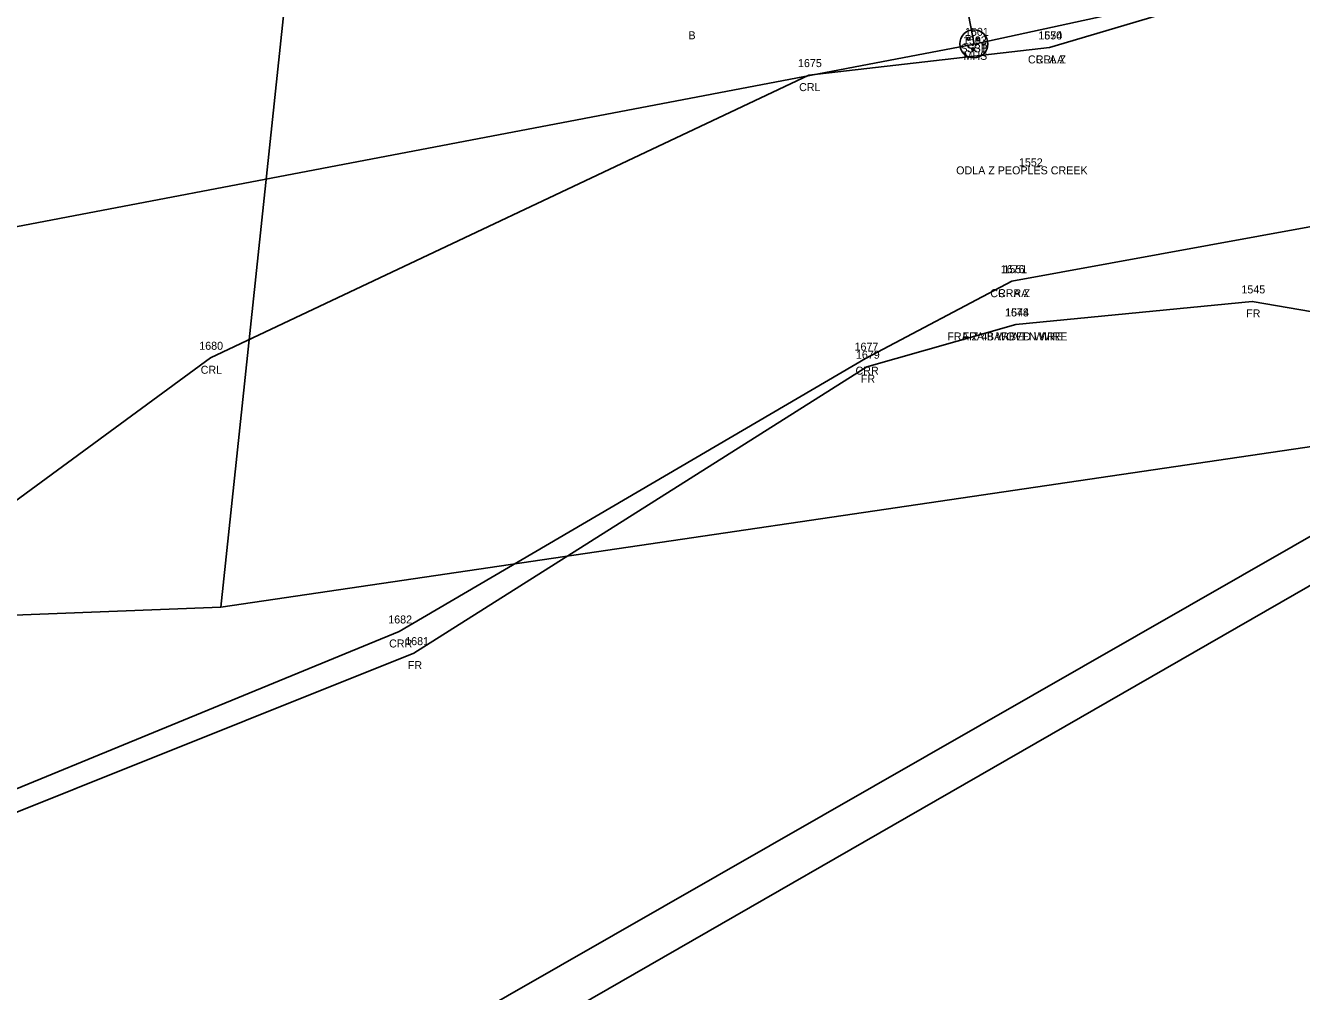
# Model space of a CAD drawing. Extents: x 1812113 to 1819860, y 1177290 to 1181185.
# Drawn here: x 1813371.7 to 1813531.1, y 1178588.3 to 1178709.1 of the extents above; entities that cross this region are included whole.
import ezdxf

# ---------------------------------------------------------------- set-up
doc = ezdxf.new("R2010")
doc.units = 0
for name, color, linetype in [('RD_EX_Bldg_txCode', 7, 'Continuous'), ('RD_EX_DR_Inlet', 7, 'Continuous'), ('RD_EX_DV_Prop', 7, 'Continuous'), ('RD_EX_Fence_Other', 7, 'Continuous'), ('RD_EX_Fence_Other_txCode', 7, 'Continuous'), ('RD_EX_H2O', 7, 'Continuous'), ('RD_EX_H2O_txCode', 7, 'Continuous'), ('RD_EX_Misc', 7, 'Continuous'), ('RD_EX_UT', 7, 'Continuous'), ('RD_EX_UT_txCode', 7, 'Continuous'), ('RD_SMD_Locator', 7, 'Continuous')]:
    doc.layers.add(name, color=color, linetype=linetype)

msp = doc.modelspace()

# ---------------------------------------------------------------- linework, layer by layer
at = {"layer": 'RD_EX_DR_Inlet'}
for centre, radius in [((1813490.17, 1178706.82), 1.75), ((1813489.51, 1178707.45), 0.175), ((1813490.09, 1178706.16), 0.175), ((1813490.73, 1178707.38), 0.175)]:
    msp.add_circle(centre, radius, dxfattribs=at)
at = {"layer": 'RD_EX_DV_Prop'}
for p, q in [((1813409.98, 1178767.65), (1813396.08, 1178636.38)), ((1813396.08, 1178636.38), (1813534.09, 1178656.72)), ((1813247.98, 1178630.56), (1813396.08, 1178636.38))]:
    msp.add_line(p, q, dxfattribs=at)
at = {"layer": 'RD_EX_Fence_Other'}
for points in [[(1813495.44, 1178671.73), (1813524.97, 1178674.61), (1813567.3, 1178667.34), (1813625.77, 1178659.53), (1813676.75, 1178657.94), (1813689.16, 1178653.47)], [(1813495.44, 1178671.73), (1813476.81, 1178666.44), (1813420.19, 1178630.62), (1813335.47, 1178596.68), (1813279.97, 1178607.5)]]:
    msp.add_lwpolyline(points, dxfattribs=at)
at = {"layer": 'RD_EX_H2O'}
for points in [[(1813499.62, 1178706.37), (1813533.11, 1178716.31), (1813566.87, 1178706.45), (1813581.02, 1178703.79), (1813602.73, 1178697.66), (1813630.18, 1178688.94), (1813658.74, 1178690.22), (1813683.52, 1178690.56), (1813733.77, 1178695.63), (1813767.86, 1178725.16), (1813778.94, 1178729.95)], [(1813499.62, 1178706.37), (1813469.57, 1178702.91), (1813394.78, 1178667.56), (1813339.87, 1178627.25), (1813279.53, 1178636.34)], [(1813494.93, 1178677.14), (1813538.08, 1178685.02), (1813548.67, 1178684.4), (1813554.06, 1178674.83), (1813572.78, 1178667.8), (1813599.8, 1178663.18), (1813623.26, 1178662.12), (1813655.35, 1178662.6), (1813687.65, 1178668.53), (1813720.68, 1178667.78), (1813740.16, 1178669.89), (1813749.02, 1178672.08), (1813765.42, 1178660.89)], [(1813494.93, 1178677.14), (1813476.64, 1178667.45), (1813418.36, 1178633.33), (1813336.03, 1178599.49), (1813281.53, 1178610.55)]]:
    msp.add_lwpolyline(points, dxfattribs=at)
at = {"layer": 'RD_EX_Misc'}
for points in [[(1813405.71, 1178572.74), (1813779.17, 1178786.7), (1813799.35, 1179222.21)], [(1813408.47, 1178567.92), (1813786.33, 1178785.29), (1813804.76, 1179221.83)]]:
    msp.add_lwpolyline(points, dxfattribs=at)
at = {"layer": 'RD_EX_UT'}
for points in [[(1812996.89, 1178919.95), (1813204.49, 1178832.44), (1813481.3, 1178753.03), (1813490.2, 1178706.76)], [(1813817.45, 1178777.9), (1813490.2, 1178706.76), (1813294.33, 1178669.42)]]:
    msp.add_lwpolyline(points, dxfattribs=at)
at = {"layer": 'RD_SMD_Locator'}
for centre in [(1813490.2, 1178706.76), (1813490.2, 1178706.76), (1813499.62, 1178706.37), (1813499.62, 1178706.37), (1813469.57, 1178702.91), (1813497.15, 1178691.5), (1813494.93, 1178677.14), (1813494.93, 1178677.14), (1813524.97, 1178674.61), (1813495.44, 1178671.73), (1813495.44, 1178671.73), (1813394.78, 1178667.56), (1813476.64, 1178667.45), (1813476.81, 1178666.44), (1813418.36, 1178633.33), (1813420.19, 1178630.62)]:
    msp.add_circle(centre, 0.001, dxfattribs=at)

# ---------------------------------------------------------------- texts
at = {"layer": 'RD_EX_Bldg_txCode'}
msp.add_text('B', height=1, dxfattribs=at).set_placement((1813454.51, 1178707.39))
at = {"layer": 'RD_EX_Fence_Other_txCode'}
for s, p in [('1545', (1813523.62, 1178675.61)), ('1678', (1813494.07, 1178672.73)), ('1544', (1813494.1, 1178672.73)), ('FR', (1813524.21, 1178672.61)), ('FRA Z 48 WOVEN WIRE', (1813486.87, 1178669.73)), ('FRA BARBED WIRE', (1813488.77, 1178669.73)), ('1679', (1813475.44, 1178667.44)), ('FR', (1813476.05, 1178664.44)), ('1681', (1813419.11, 1178631.62)), ('FR', (1813419.44, 1178628.62))]:
    msp.add_text(s, height=1, dxfattribs=at).set_placement(p)
at = {"layer": 'RD_EX_H2O_txCode'}
for s, p in [('1550', (1813498.23, 1178707.37)), ('1674', (1813498.25, 1178707.37)), ('1675', (1813468.2, 1178703.91)), ('CRLA Z', (1813496.94, 1178704.37)), ('CRLA', (1813497.9, 1178704.37)), ('CRL', (1813468.34, 1178700.91)), ('1552', (1813495.81, 1178691.5)), ('ODLA Z PEOPLES CREEK', (1813487.97, 1178690.5)), ('1676', (1813493.54, 1178678.14)), ('1551', (1813493.87, 1178678.14)), ('CRRA Z', (1813492.23, 1178675.14)), ('CRRA', (1813493.19, 1178675.14)), ('1680', (1813393.37, 1178668.56)), ('1677', (1813475.27, 1178668.45)), ('CRL', (1813393.55, 1178665.56)), ('CRR', (1813475.39, 1178665.45)), ('1682', (1813416.99, 1178634.33)), ('CRR', (1813417.1, 1178631.33))]:
    msp.add_text(s, height=1, dxfattribs=at).set_placement(p)
at = {"layer": 'RD_EX_UT_txCode'}
for s, p in [('1501', (1813489.07, 1178707.82)), ('SS3B', (1813488.5, 1178705.76)), ('1502', (1813488.82, 1178706.76)), ('1503', (1813488.82, 1178706.76)), ('SS1', (1813489.26, 1178705.76)), ('MHS', (1813488.88, 1178704.82))]:
    msp.add_text(s, height=1, dxfattribs=at).set_placement(p)

doc.saveas('drawing.dxf')
